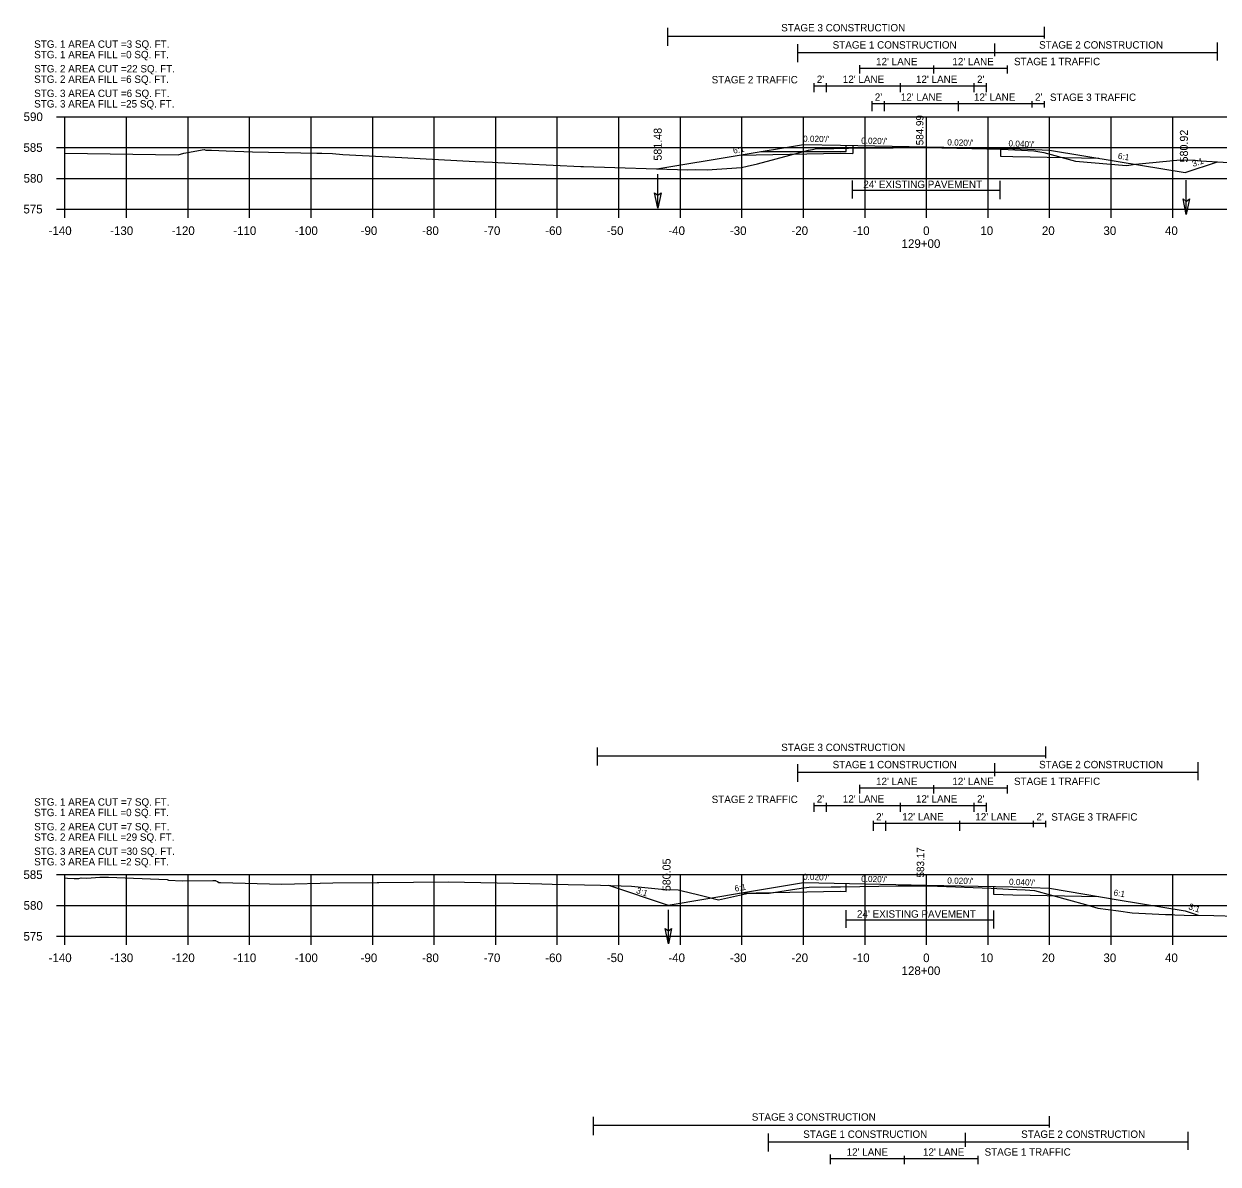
# Model space of a CAD drawing. Extents: x 642114 to 642416, y 286928 to 293347.
# Drawn here: x 642113.6 to 642307.6, y 291927.9 to 292113.1 of the extents above; entities that cross this region are included whole.
import ezdxf

# ---------------------------------------------------------------- set-up
doc = ezdxf.new("R2010")
doc.units = 0
for name, color, linetype in [('59', 7, 'Continuous'), ('Level 43', 7, 'Continuous'), ('Level 58', 7, 'Continuous'), ('R_Axis', 7, 'Continuous'), ('R_Axis Annot', 7, 'Continuous'), ('R_Draft', 7, 'Continuous'), ('R_Exist Surface', 7, 'Continuous'), ('R_Exist Surface Annot', 7, 'Continuous'), ('R_Fin Surface', 7, 'Continuous'), ('R_Grid', 7, 'Continuous'), ('R_Xsect Elev', 7, 'Continuous'), ('R_Xsect Slope', 7, 'Continuous')]:
    doc.layers.add(name, color=color, linetype=linetype)

# ---------------------------------------------------------------- blocks, each defined once
blk = doc.blocks.new('FA')
at = {"layer": 'Level 43'}
blk.add_lwpolyline([(7.94, 0), (0, 0)], dxfattribs=at)
at = {"layer": 'Level 58'}
blk.add_lwpolyline([(4.34, 0.75), (7.94, 0), (4.34, -0.75), (4.94, 0)], close=True, dxfattribs=at)

msp = doc.modelspace()

# ---------------------------------------------------------------- linework, layer by layer
at = {"layer": 'R_Axis'}
for p, q in [((642118.84, 292098.01), (642120.24, 292098.01)), ((642120.24, 292083.01), (642120.24, 292098.01)), ((642118.84, 292093.01), (642120.24, 292093.01)), ((642118.84, 292088.01), (642120.24, 292088.01)), ((642118.84, 292083.01), (642120.24, 292083.01)), ((642120.24, 292083.01), (642400.24, 292083.01)), ((642120.24, 292081.61), (642120.24, 292083.01)), ((642130.24, 292081.61), (642130.24, 292083.01)), ((642140.24, 292081.61), (642140.24, 292083.01)), ((642150.24, 292081.61), (642150.24, 292083.01)), ((642160.24, 292081.61), (642160.24, 292083.01)), ((642170.24, 292081.61), (642170.24, 292083.01)), ((642180.24, 292081.61), (642180.24, 292083.01)), ((642190.24, 292081.61), (642190.24, 292083.01)), ((642200.24, 292081.61), (642200.24, 292083.01)), ((642210.24, 292081.61), (642210.24, 292083.01)), ((642220.24, 292081.61), (642220.24, 292083.01)), ((642230.24, 292081.61), (642230.24, 292083.01)), ((642240.24, 292081.61), (642240.24, 292083.01)), ((642250.24, 292081.61), (642250.24, 292083.01)), ((642260.24, 292081.61), (642260.24, 292083.01)), ((642270.24, 292081.61), (642270.24, 292083.01)), ((642280.24, 292081.61), (642280.24, 292083.01)), ((642290.24, 292081.61), (642290.24, 292083.01)), ((642300.24, 292081.61), (642300.24, 292083.01)), ((642118.84, 291974.93), (642120.24, 291974.93)), ((642118.84, 291974.93), (642120.24, 291974.93)), ((642120.24, 291964.93), (642120.24, 291974.93)), ((642120.24, 291964.93), (642120.24, 291974.93)), ((642118.84, 291969.93), (642120.24, 291969.93)), ((642118.84, 291969.93), (642120.24, 291969.93)), ((642118.84, 291964.93), (642120.24, 291964.93)), ((642118.84, 291964.93), (642120.24, 291964.93)), ((642120.24, 291964.93), (642400.24, 291964.93)), ((642120.24, 291963.53), (642120.24, 291964.93)), ((642120.24, 291964.93), (642400.24, 291964.93)), ((642120.24, 291963.53), (642120.24, 291964.93)), ((642130.24, 291963.53), (642130.24, 291964.93)), ((642130.24, 291963.53), (642130.24, 291964.93)), ((642140.24, 291963.53), (642140.24, 291964.93)), ((642140.24, 291963.53), (642140.24, 291964.93)), ((642150.24, 291963.53), (642150.24, 291964.93)), ((642150.24, 291963.53), (642150.24, 291964.93)), ((642160.24, 291963.53), (642160.24, 291964.93)), ((642160.24, 291963.53), (642160.24, 291964.93)), ((642170.24, 291963.53), (642170.24, 291964.93)), ((642170.24, 291963.53), (642170.24, 291964.93)), ((642180.24, 291963.53), (642180.24, 291964.93)), ((642180.24, 291963.53), (642180.24, 291964.93)), ((642190.24, 291963.53), (642190.24, 291964.93)), ((642190.24, 291963.53), (642190.24, 291964.93)), ((642200.24, 291963.53), (642200.24, 291964.93)), ((642200.24, 291963.53), (642200.24, 291964.93)), ((642210.24, 291963.53), (642210.24, 291964.93)), ((642210.24, 291963.53), (642210.24, 291964.93)), ((642220.24, 291963.53), (642220.24, 291964.93)), ((642220.24, 291963.53), (642220.24, 291964.93)), ((642230.24, 291963.53), (642230.24, 291964.93)), ((642230.24, 291963.53), (642230.24, 291964.93)), ((642240.24, 291963.53), (642240.24, 291964.93)), ((642240.24, 291963.53), (642240.24, 291964.93)), ((642250.24, 291963.53), (642250.24, 291964.93)), ((642250.24, 291963.53), (642250.24, 291964.93)), ((642260.24, 291963.53), (642260.24, 291964.93)), ((642260.24, 291963.53), (642260.24, 291964.93)), ((642270.24, 291963.53), (642270.24, 291964.93)), ((642270.24, 291963.53), (642270.24, 291964.93)), ((642280.24, 291963.53), (642280.24, 291964.93)), ((642280.24, 291963.53), (642280.24, 291964.93)), ((642290.24, 291963.53), (642290.24, 291964.93)), ((642290.24, 291963.53), (642290.24, 291964.93)), ((642300.24, 291963.53), (642300.24, 291964.93)), ((642300.24, 291963.53), (642300.24, 291964.93))]:
    msp.add_line(p, q, dxfattribs=at)
at = {"layer": 'R_Exist Surface'}
for points in [[(642248.24, 292093.36), (642248.24, 292092.07)], [(642272.24, 292092.88), (642272.24, 292091.59)], [(642229.8, 292091.78), (642246.24, 292092.11), (642248.24, 292092.07)], [(642272.24, 292091.59), (642274.24, 292091.55), (642288.23, 292091.27)], [(642229.8, 291971.91), (642246.24, 291972.24), (642247.18, 291972.22)], [(642247.14, 291973.51), (642247.14, 291972.22)], [(642271.14, 291973.03), (642271.14, 291971.74)], [(642271.14, 291971.74), (642274.24, 291971.68), (642288.23, 291971.4)]]:
    msp.add_lwpolyline(points, dxfattribs=at)
at = {"layer": 'R_Exist Surface Annot'}
for points in [[(642120.24, 292092.11), (642138.64, 292091.85), (642139.54, 292092.08), (642142.84, 292092.67), (642143.14, 292092.58), (642144.03, 292092.59), (642146.44, 292092.46), (642150.72, 292092.31), (642161.19, 292092.12), (642161.96, 292092.11), (642163.72, 292092.06), (642165.37, 292091.9), (642174.97, 292091.39), (642186.9, 292090.74), (642189.72, 292090.61), (642190.55, 292090.56), (642204.07, 292089.94), (642204.19, 292089.94), (642204.4, 292089.93), (642204.5, 292089.92), (642221.44, 292089.39), (642222.66, 292089.42), (642224.58, 292089.41), (642230.16, 292089.76), (642231.1, 292090), (642232.77, 292090.35), (642241.05, 292092.58), (642241.68, 292092.7), (642242.15, 292092.79), (642245.18, 292092.87), (642247.55, 292092.93), (642254.82, 292092.97), (642260.26, 292093.01), (642267.59, 292092.85), (642272.39, 292092.73), (642275.67, 292092.57), (642277.69, 292092.45), (642278.67, 292092.3), (642279.28, 292092.2), (642284.42, 292090.82), (642292.72, 292090.09), (642293.51, 292090.21), (642294.21, 292090.3), (642301.44, 292091.03), (642303.91, 292090.95), (642304.79, 292090.87), (642309.35, 292090.59)], [(642120.24, 291974.39), (642120.63, 291974.37), (642121.76, 291974.31), (642122.5, 291974.31), (642122.88, 291974.4), (642123.79, 291974.37), (642125.9, 291974.5), (642127.31, 291974.5), (642136.82, 291974.13), (642137.05, 291974.02), (642139.28, 291973.91), (642144.28, 291973.97), (642144.71, 291973.97), (642144.78, 291973.95), (642145.03, 291973.84), (642145.23, 291973.67), (642145.49, 291973.64), (642155.5, 291973.38), (642163.78, 291973.61), (642170.99, 291973.66), (642171.24, 291973.66), (642182.51, 291973.76), (642195.78, 291973.47), (642197.72, 291973.42), (642199.41, 291973.4), (642207.28, 291973.24), (642212.32, 291973.08), (642217.73, 291972.53), (642219.89, 291972.45), (642220.29, 291972.34), (642223.24, 291971.64), (642223.69, 291971.56), (642226.42, 291970.84), (642231.33, 291971.95), (642234.66, 291971.91), (642239.84, 291972.72), (642240.73, 291972.83), (642241.16, 291972.88), (642244.72, 291972.95), (642246.28, 291972.96), (642255.62, 291973.09), (642259.14, 291973.14), (642262.03, 291973.04), (642270.73, 291972.72), (642273.54, 291972.6), (642276.24, 291972.48), (642277.01, 291972.42), (642277.75, 291972.38), (642286.09, 291970.06), (642288.08, 291969.47), (642291.43, 291969.08), (642293.63, 291968.71), (642299.07, 291968.47), (642299.17, 291968.45), (642300.07, 291968.46), (642300.59, 291968.41), (642302.08, 291968.37), (642306.89, 291968.32), (642310.53, 291968.19)]]:
    msp.add_lwpolyline(points, dxfattribs=at)
at = {"layer": 'R_Fin Surface'}
for points in [[(642216.4, 292089.55), (642229.8, 292091.78), (642240.24, 292093.52), (642246.24, 292093.4)], [(642246.24, 292093.4), (642260.24, 292093.12), (642274.24, 292092.84), (642280.24, 292092.6), (642291.38, 292090.75), (642302.24, 292088.94), (642307.53, 292090.7)], [(642208.58, 291973.2), (642218.24, 291969.98), (642230.83, 291972.08), (642240.24, 291973.65)], [(642240.24, 291973.65), (642260.24, 291973.25), (642274.24, 291972.97), (642280.24, 291972.73), (642291.38, 291970.87), (642302.24, 291969.06), (642304.38, 291968.35)]]:
    msp.add_lwpolyline(points, dxfattribs=at)
at = {"layer": 'R_Grid'}
for p, q in [((642120.24, 292098.01), (642400.24, 292098.01)), ((642130.24, 292083.01), (642130.24, 292098.01)), ((642140.24, 292083.01), (642140.24, 292098.01)), ((642150.24, 292083.01), (642150.24, 292098.01)), ((642160.24, 292083.01), (642160.24, 292098.01)), ((642170.24, 292083.01), (642170.24, 292098.01)), ((642180.24, 292083.01), (642180.24, 292098.01)), ((642190.24, 292083.01), (642190.24, 292098.01)), ((642200.24, 292083.01), (642200.24, 292098.01)), ((642210.24, 292083.01), (642210.24, 292098.01)), ((642220.24, 292083.01), (642220.24, 292098.01)), ((642230.24, 292083.01), (642230.24, 292098.01)), ((642240.24, 292083.01), (642240.24, 292098.01)), ((642250.24, 292083.01), (642250.24, 292098.01)), ((642260.24, 292083.01), (642260.24, 292098.01)), ((642270.24, 292083.01), (642270.24, 292098.01)), ((642280.24, 292083.01), (642280.24, 292098.01)), ((642290.24, 292083.01), (642290.24, 292098.01)), ((642300.24, 292083.01), (642300.24, 292098.01)), ((642120.24, 292093.01), (642400.24, 292093.01)), ((642120.24, 292088.01), (642400.24, 292088.01)), ((642120.24, 291974.93), (642400.24, 291974.93)), ((642120.24, 291964.93), (642120.24, 291974.93)), ((642120.24, 291974.93), (642400.24, 291974.93)), ((642120.24, 291964.93), (642120.24, 291974.93)), ((642130.24, 291964.93), (642130.24, 291974.93)), ((642130.24, 291964.93), (642130.24, 291974.93)), ((642140.24, 291964.93), (642140.24, 291974.93)), ((642140.24, 291964.93), (642140.24, 291974.93)), ((642150.24, 291964.93), (642150.24, 291974.93)), ((642150.24, 291964.93), (642150.24, 291974.93)), ((642160.24, 291964.93), (642160.24, 291974.93)), ((642160.24, 291964.93), (642160.24, 291974.93)), ((642170.24, 291964.93), (642170.24, 291974.93)), ((642170.24, 291964.93), (642170.24, 291974.93)), ((642180.24, 291964.93), (642180.24, 291974.93)), ((642180.24, 291964.93), (642180.24, 291974.93)), ((642190.24, 291964.93), (642190.24, 291974.93)), ((642190.24, 291964.93), (642190.24, 291974.93)), ((642200.24, 291964.93), (642200.24, 291974.93)), ((642200.24, 291964.93), (642200.24, 291974.93)), ((642210.24, 291964.93), (642210.24, 291974.93)), ((642210.24, 291964.93), (642210.24, 291974.93)), ((642220.24, 291964.93), (642220.24, 291974.93)), ((642220.24, 291964.93), (642220.24, 291974.93)), ((642230.24, 291964.93), (642230.24, 291974.93)), ((642230.24, 291964.93), (642230.24, 291974.93)), ((642240.24, 291964.93), (642240.24, 291974.93)), ((642240.24, 291964.93), (642240.24, 291974.93)), ((642250.24, 291964.93), (642250.24, 291974.93)), ((642250.24, 291964.93), (642250.24, 291974.93)), ((642260.24, 291964.93), (642260.24, 291974.93)), ((642260.24, 291964.93), (642260.24, 291974.93)), ((642270.24, 291964.93), (642270.24, 291974.93)), ((642270.24, 291964.93), (642270.24, 291974.93)), ((642280.24, 291964.93), (642280.24, 291974.93)), ((642280.24, 291964.93), (642280.24, 291974.93)), ((642290.24, 291964.93), (642290.24, 291974.93)), ((642290.24, 291964.93), (642290.24, 291974.93)), ((642300.24, 291964.93), (642300.24, 291974.93)), ((642300.24, 291964.93), (642300.24, 291974.93)), ((642120.24, 291969.93), (642400.24, 291969.93)), ((642120.24, 291969.93), (642400.24, 291969.93)), ((642120.24, 291964.93), (642400.24, 291964.93)), ((642120.24, 291964.93), (642400.24, 291964.93))]:
    msp.add_line(p, q, dxfattribs=at)
at = {"layer": 'R_Xsect Elev'}
for p, q in [((642218.21, 292109.54), (642218.21, 292112.47)), ((642279.41, 292110.74), (642279.41, 292112.61)), ((642218.21, 292111.12), (642279.41, 292111.12)), ((642271.33, 292107.87), (642271.33, 292109.92)), ((642307.53, 292107.12), (642307.53, 292110.05)), ((642239.32, 292106.85), (642239.32, 292109.78)), ((642239.32, 292108.46), (642271.33, 292108.46)), ((642271.33, 292108.46), (642307.53, 292108.46)), ((642249.41, 292105.06), (642249.41, 292106.37)), ((642249.41, 292105.01), (642249.41, 292106.33)), ((642261.41, 292105.01), (642261.41, 292106.33)), ((642273.41, 292105.01), (642273.41, 292106.33)), ((642249.41, 292105.91), (642273.41, 292105.91)), ((642241.98, 292102.03), (642241.98, 292103.46)), ((642241.98, 292103.04), (642269.98, 292103.04)), ((642243.98, 292102.03), (642243.98, 292103.46)), ((642255.98, 292102.03), (642255.98, 292103.46)), ((642267.98, 292102.03), (642267.98, 292103.46)), ((642269.98, 292102.03), (642269.98, 292103.46)), ((642251.41, 292098.9), (642251.41, 292100.56)), ((642253.41, 292098.9), (642253.41, 292100.56)), ((642265.41, 292098.9), (642265.41, 292100.56)), ((642277.41, 292099.54), (642277.41, 292100.56)), ((642279.41, 292099.54), (642279.41, 292100.56)), ((642251.41, 292100.14), (642279.41, 292100.14)), ((642248.21, 292084.74), (642248.21, 292087.67)), ((642272.21, 292084.65), (642272.21, 292087.58)), ((642248.21, 292086.09), (642272.21, 292086.09)), ((642206.75, 291992.67), (642206.75, 291995.6)), ((642279.63, 291993.87), (642279.63, 291995.74)), ((642206.75, 291994.25), (642279.63, 291994.25)), ((642239.32, 291989.98), (642239.32, 291992.9)), ((642239.32, 291991.59), (642271.33, 291991.59)), ((642271.33, 291990.95), (642271.33, 291993.05)), ((642271.33, 291991.59), (642304.38, 291991.59)), ((642304.38, 291990.25), (642304.38, 291993.18)), ((642249.41, 291988.19), (642249.41, 291989.5)), ((642249.41, 291988.12), (642249.41, 291989.44)), ((642249.41, 291989.03), (642273.41, 291989.03)), ((642261.41, 291988.12), (642261.41, 291989.44)), ((642273.41, 291988.12), (642273.41, 291989.44)), ((642241.98, 291985.16), (642241.98, 291986.59)), ((642241.98, 291986.17), (642269.98, 291986.17)), ((642243.98, 291985.16), (642243.98, 291986.59)), ((642255.98, 291985.16), (642255.98, 291986.59)), ((642267.98, 291985.16), (642267.98, 291986.59)), ((642269.98, 291985.16), (642269.98, 291986.59)), ((642251.63, 291982.03), (642251.63, 291983.69)), ((642251.63, 291983.27), (642279.63, 291983.27)), ((642253.63, 291982.03), (642253.63, 291983.69)), ((642265.63, 291982.03), (642265.63, 291983.69)), ((642277.63, 291982.67), (642277.63, 291983.69)), ((642279.63, 291982.67), (642279.63, 291983.69)), ((642247.18, 291966.27), (642247.18, 291969.19)), ((642271.18, 291966.18), (642271.18, 291969.1)), ((642247.18, 291967.62), (642271.18, 291967.62)), ((642206.14, 291932.65), (642206.14, 291935.58)), ((642280.24, 291933.85), (642280.24, 291935.72)), ((642206.14, 291934.23), (642280.24, 291934.23)), ((642234.54, 291929.96), (642234.54, 291932.88)), ((642234.54, 291931.57), (642266.55, 291931.57)), ((642266.55, 291930.74), (642266.55, 291933.03)), ((642266.55, 291931.57), (642302.74, 291931.57)), ((642302.74, 291930.23), (642302.74, 291933.16)), ((642244.63, 291928.17), (642244.63, 291929.48)), ((642244.63, 291927.93), (642244.63, 291929.25)), ((642244.63, 291928.83), (642268.63, 291928.83)), ((642256.63, 291927.93), (642256.63, 291929.25)), ((642268.63, 291927.93), (642268.63, 291929.25))]:
    msp.add_line(p, q, dxfattribs=at)
for points in [[(642233.32, 292092.37), (642247.18, 292092.37), (642247.18, 292093.37)], [(642247.18, 291972.22), (642247.18, 291972.96)]]:
    msp.add_lwpolyline(points, dxfattribs=at)

# ---------------------------------------------------------------- block references
at = {"layer": 'R_Xsect Elev', "xscale": 0.7, "yscale": 0.7, "rotation": -90.00000000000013}
for p in [(642216.58, 292088.71), (642302.44, 292087.72), (642218.28, 291969.24)]:
    msp.add_blockref('FA', p, dxfattribs=at)

# ---------------------------------------------------------------- texts
at = {"layer": '59'}
for s, p in [(' 581.48', (642217.21, 292090.4)), (' 580.92', (642302.7, 292090.11)), (' 580.05', (642218.64, 291971.76))]:
    msp.add_text(s, height=1.3, rotation=90, dxfattribs=at).set_placement(p)
at = {"layer": 'R_Axis Annot'}
for s, p in [('590', (642113.52, 292097.31)), ('585', (642113.49, 292092.31)), ('580', (642113.52, 292087.31)), ('575', (642113.49, 292082.31)), ('-140', (642117.58, 292078.81)), ('-130', (642127.58, 292078.81)), ('-120', (642137.58, 292078.81)), ('-110', (642147.58, 292078.81)), ('-100', (642157.58, 292078.81)), ('-90', (642168.28, 292078.81)), ('-80', (642178.28, 292078.81)), ('-70', (642188.28, 292078.81)), ('-60', (642198.28, 292078.81)), ('-50', (642208.28, 292078.81)), ('-40', (642218.28, 292078.81)), ('-30', (642228.28, 292078.81)), ('-20', (642238.28, 292078.81)), ('-10', (642248.28, 292078.81)), ('0', (642259.68, 292078.81)), ('10', (642268.98, 292078.81)), ('20', (642278.98, 292078.81)), ('30', (642288.98, 292078.81)), ('40', (642298.98, 292078.81)), ('129+00', (642256.18, 292076.71)), ('585', (642113.49, 291974.23)), ('585', (642113.49, 291974.23)), ('580', (642113.52, 291969.23)), ('580', (642113.52, 291969.23)), ('575', (642113.49, 291964.23)), ('575', (642113.49, 291964.23)), ('-140', (642117.58, 291960.73)), ('-140', (642117.58, 291960.73)), ('-130', (642127.58, 291960.73)), ('-130', (642127.58, 291960.73)), ('-120', (642137.58, 291960.73)), ('-120', (642137.58, 291960.73)), ('-110', (642147.58, 291960.73)), ('-110', (642147.58, 291960.73)), ('-100', (642157.58, 291960.73)), ('-100', (642157.58, 291960.73)), ('-90', (642168.28, 291960.73)), ('-90', (642168.28, 291960.73)), ('-80', (642178.28, 291960.73)), ('-80', (642178.28, 291960.73)), ('-70', (642188.28, 291960.73)), ('-70', (642188.28, 291960.73)), ('-60', (642198.28, 291960.73)), ('-60', (642198.28, 291960.73)), ('-50', (642208.28, 291960.73)), ('-50', (642208.28, 291960.73)), ('-40', (642218.28, 291960.73)), ('-40', (642218.28, 291960.73)), ('-30', (642228.28, 291960.73)), ('-30', (642228.28, 291960.73)), ('-20', (642238.28, 291960.73)), ('-20', (642238.28, 291960.73)), ('-10', (642248.28, 291960.73)), ('-10', (642248.28, 291960.73)), ('0', (642259.68, 291960.73)), ('0', (642259.68, 291960.73)), ('10', (642268.98, 291960.73)), ('10', (642268.98, 291960.73)), ('20', (642278.98, 291960.73)), ('20', (642278.98, 291960.73)), ('30', (642288.98, 291960.73)), ('30', (642288.98, 291960.73)), ('40', (642298.98, 291960.73)), ('40', (642298.98, 291960.73)), ('128+00', (642256.18, 291958.63)), ('128+00', (642256.18, 291958.63))]:
    msp.add_text(s, height=1.4, dxfattribs=at).set_placement(p)
at = {"layer": 'R_Draft'}
for s, p in [('STG. 1 AREA CUT =3 SQ. FT.', (642115.24, 292109.21)), ('STG. 1 AREA FILL =0 SQ. FT.', (642115.24, 292107.51)), ('STG. 2 AREA CUT =22 SQ. FT.', (642115.24, 292105.21)), ('STG. 2 AREA FILL =6 SQ. FT.', (642115.24, 292103.51)), ('STG. 3 AREA CUT =6 SQ. FT.', (642115.24, 292101.21)), ('STG. 3 AREA FILL =25 SQ. FT.', (642115.24, 292099.51)), ('STG. 1 AREA CUT =7 SQ. FT.', (642115.24, 291986.13)), ('STG. 1 AREA FILL =0 SQ. FT.', (642115.24, 291984.43)), ('STG. 2 AREA CUT =7 SQ. FT.', (642115.24, 291982.13)), ('STG. 2 AREA FILL =29 SQ. FT.', (642115.24, 291980.43)), ('STG. 3 AREA CUT =30 SQ. FT.', (642115.24, 291978.13)), ('STG. 3 AREA FILL =2 SQ. FT.', (642115.24, 291976.43))]:
    msp.add_text(s, height=1.2, dxfattribs=at).set_placement(p)
at = {"layer": 'R_Xsect Elev'}
for s, p in [('STAGE 3 CONSTRUCTION', (642236.62, 292111.87)), ('STAGE 1 CONSTRUCTION', (642244.98, 292109.08)), ('STAGE 2 CONSTRUCTION', (642278.52, 292109.08)), ("12' LANE", (642252.03, 292106.37)), ("12' LANE", (642264.43, 292106.37)), ('STAGE 1 TRAFFIC', (642274.45, 292106.38)), ('STAGE 2 TRAFFIC', (642225.32, 292103.43)), ("2'", (642242.4, 292103.5)), ("12' LANE", (642246.63, 292103.5)), ("12' LANE", (642258.51, 292103.5)), ("2'", (642268.44, 292103.5)), ("2'", (642251.83, 292100.6)), ("12' LANE", (642256.05, 292100.6)), ("12' LANE", (642267.94, 292100.6)), ("2'", (642277.86, 292100.6)), ('STAGE 3 TRAFFIC', (642280.29, 292100.58)), ("24' EXISTING PAVEMENT", (642249.96, 292086.43)), ('STAGE 3 CONSTRUCTION', (642236.62, 291995)), ('STAGE 1 CONSTRUCTION', (642244.98, 291992.21)), ('STAGE 2 CONSTRUCTION', (642278.52, 291992.21)), ("12' LANE", (642252.03, 291989.48)), ("12' LANE", (642264.43, 291989.48)), ('STAGE 1 TRAFFIC', (642274.45, 291989.49)), ('STAGE 2 TRAFFIC', (642225.32, 291986.56)), ("2'", (642242.4, 291986.63)), ("12' LANE", (642246.63, 291986.63)), ("12' LANE", (642258.51, 291986.63)), ("2'", (642268.44, 291986.63)), ("2'", (642252.05, 291983.73)), ("12' LANE", (642256.28, 291983.73)), ("12' LANE", (642268.16, 291983.73)), ("2'", (642278.09, 291983.73)), ('STAGE 3 TRAFFIC', (642280.51, 291983.71)), ("24' EXISTING PAVEMENT", (642248.93, 291967.95)), ('STAGE 3 CONSTRUCTION', (642231.84, 291934.98)), ('STAGE 1 CONSTRUCTION', (642240.2, 291932.19)), ('STAGE 2 CONSTRUCTION', (642275.61, 291932.19)), ("12' LANE", (642247.25, 291929.29)), ("12' LANE", (642259.65, 291929.29)), ('STAGE 1 TRAFFIC', (642269.67, 291929.3))]:
    msp.add_text(s, height=1.2, dxfattribs=at).set_placement(p)
for s, p in [('584.99', (642259.73, 292093.38)), ('583.17', (642259.85, 291974.47))]:
    msp.add_text(s, height=1.2, rotation=90, dxfattribs=at).set_placement(p)
at = {"layer": 'R_Xsect Slope'}
for s, rotation, p in [("0.020'/'", 358.8533, (642240.16, 292093.96)), ("0.020'/'", 358.8542, (642249.6, 292093.64)), ("0.020'/'", 358.8542, (642263.6, 292093.36)), ('6:1', 9.4642, (642228.88, 292092.02)), ("0.040'/'", 357.7094, (642273.53, 292093.2)), ('6:1', 350.5358, (642291.27, 292091.2)), ('3:1', 18.4332, (642303.57, 292089.86)), ("0.020'/'", 358.8533, (642240.16, 291974.08)), ("0.020'/'", 358.8542, (642249.6, 291973.76)), ("0.020'/'", 358.8542, (642263.6, 291973.48)), ("0.040'/'", 357.7094, (642273.62, 291973.29)), ('3:1', 341.5668, (642212.97, 291971.96)), ('6:1', 9.4642, (642229.13, 291972.17)), ('6:1', 350.5358, (642290.57, 291971.56)), ('3:1', 341.5668, (642302.72, 291969.35))]:
    msp.add_text(s, height=1, rotation=rotation, dxfattribs=at).set_placement(p)

doc.saveas('drawing.dxf')
